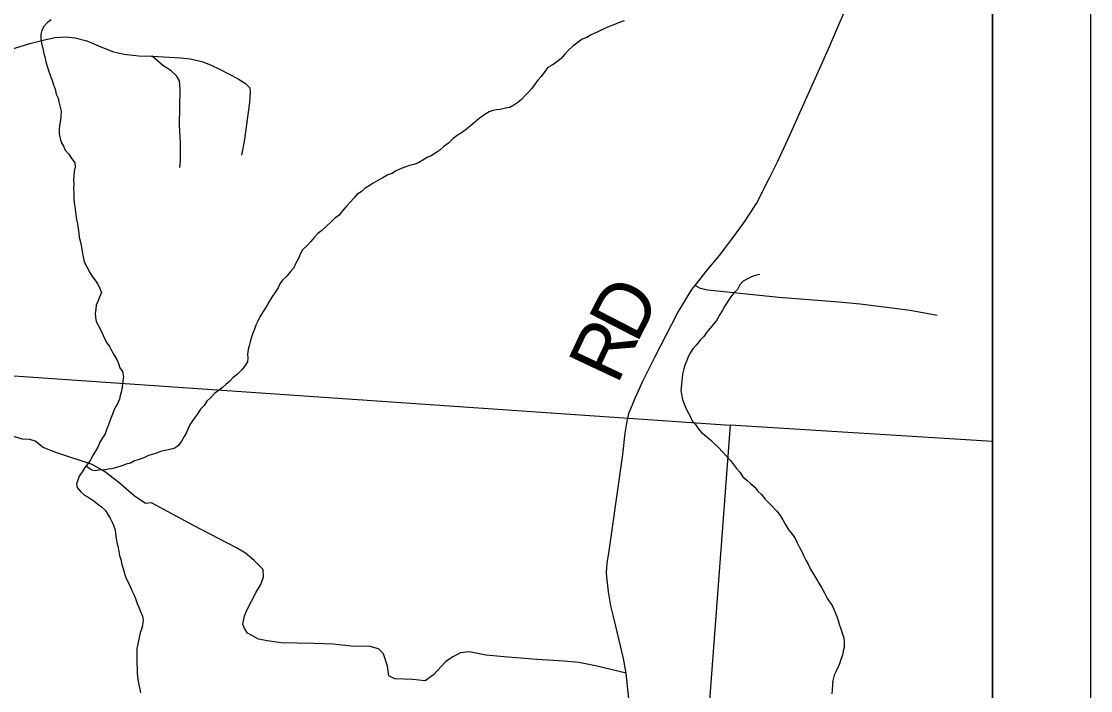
# Model space of a CAD drawing. Extents: x -13.7 to 34, y 0 to 32.3.
# Drawn here: x 29.328 to 30.417, y 19.593 to 20.274 of the extents above; entities that cross this region are included whole.
import ezdxf

# ---------------------------------------------------------------- set-up
doc = ezdxf.new("R2010")
doc.units = 0
for name, color, linetype in [('GM_X_Corporation', 7, 'Continuous'), ('GM_X_County_Road', 7, 'Continuous'), ('GM_X_County_Road_Text', 7, 'Continuous'), ('GM_X_Minor_River', 7, 'Continuous'), ('GM_X_Township_Road', 7, 'Continuous'), ('SH_Data', 7, 'Continuous')]:
    doc.layers.add(name, color=color, linetype=linetype)

msp = doc.modelspace()

# ---------------------------------------------------------------- linework, layer by layer
at = {"layer": 'GM_X_Corporation'}
for points in [[(25.5491, 14.1), (30.3167, 14.1), (30.3167, 20.877), (30.2775, 20.8796), (29.9598, 20.9), (26.0026, 20.9)], [(27.6886, 14.8962), (28.6553, 14.8354), (29.7019, 14.7755), (30.3167, 14.7354), (30.3167, 20.877), (30.2775, 20.8796), (29.9598, 20.9), (26.0026, 20.9)]]:
    msp.add_lwpolyline(points, dxfattribs=at)
for points in [[(29.0337, 19.933), (30.0496, 19.8628), (29.9735, 18.8499), (28.9612, 18.9069)], [(30.3167, 18.8265), (30.3167, 19.8464), (30.0496, 19.8628), (29.9735, 18.8499)]]:
    msp.add_lwpolyline(points, close=True, dxfattribs=at)
at = {"layer": 'GM_X_County_Road'}
msp.add_lwpolyline([(29.9468, 19.5812), (29.9436, 19.6104), (29.941, 19.6253), (29.9314, 19.6653), (29.9278, 19.6789), (29.9255, 19.6933), (29.9242, 19.7055), (29.9235, 19.7126), (29.9243, 19.7224), (29.9259, 19.7325), (29.9291, 19.7541), (29.9402, 19.833), (29.9425, 19.8548), (29.9442, 19.8649), (29.9462, 19.8747), (29.9527, 19.8904), (29.9607, 19.9078), (29.9729, 19.9321), (29.9957, 19.977), (30.0106, 20.001), (30.0139, 20.0053), (30.0261, 20.0209), (30.0388, 20.0358), (30.0531, 20.0549), (30.064, 20.07), (30.0765, 20.0886), (30.0893, 20.1141), (30.0981, 20.1317), (30.1086, 20.1544), (30.1498, 20.2461), (30.1756, 20.3066)], dxfattribs=at)
at = {"layer": 'GM_X_Minor_River'}
for points in [[(29.3578, 20.2758), (29.354, 20.2728), (29.3503, 20.269), (29.3484, 20.2652), (29.3472, 20.2606), (29.3472, 20.2568), (29.348, 20.2519), (29.3496, 20.2447), (29.3503, 20.2409), (29.3519, 20.2368), (29.3526, 20.233), (29.3538, 20.2284), (29.3553, 20.2242), (29.3568, 20.2193), (29.3584, 20.2148), (29.3599, 20.2106), (29.3618, 20.2049), (29.363, 20.2)], [(29.9415, 20.2746), (29.9373, 20.2731), (29.9335, 20.2716), (29.929, 20.2697), (29.924, 20.2678), (29.9195, 20.2659), (29.9153, 20.2636), (29.9115, 20.2621), (29.9073, 20.2601), (29.9036, 20.2575), (29.8986, 20.256), (29.8933, 20.2518), (29.8891, 20.2487), (29.885, 20.2449), (29.8812, 20.2407), (29.8774, 20.2362), (29.8713, 20.2316), (29.8676, 20.2293), (29.8638, 20.227), (29.8607, 20.2232), (29.857, 20.2179), (29.8535, 20.2141), (29.8505, 20.2103), (29.8475, 20.2058), (29.8441, 20.202), (29.8403, 20.1982), (29.8369, 20.1944), (29.8331, 20.1913), (29.8293, 20.1886), (29.8251, 20.1864), (29.8206, 20.1856), (29.8153, 20.1844), (29.8115, 20.184), (29.8077, 20.1833), (29.8039, 20.1818), (29.7986, 20.1787), (29.794, 20.1753), (29.7891, 20.1711), (29.7849, 20.1677), (29.7808, 20.1642), (29.777, 20.1612), (29.7713, 20.1578), (29.7675, 20.1547), (29.7626, 20.1502), (29.7577, 20.1467), (29.7539, 20.1429)], [(29.363, 20.2), (29.3649, 20.1958), (29.3656, 20.192), (29.3672, 20.1867), (29.368, 20.1826), (29.3676, 20.1765), (29.3672, 20.1719), (29.3665, 20.1681), (29.3661, 20.164), (29.3661, 20.1598), (29.3669, 20.1549), (29.368, 20.1511), (29.3703, 20.1469), (29.3722, 20.1431), (29.376, 20.139), (29.3783, 20.1352), (29.3821, 20.1302), (29.3822, 20.1257), (29.3814, 20.1211), (29.381, 20.1162), (29.3807, 20.1124), (29.3811, 20.1079), (29.3807, 20.1041), (29.3811, 20.0984), (29.3811, 20.0923), (29.3815, 20.0874), (29.3823, 20.0832), (29.3827, 20.0794), (29.3838, 20.0722), (29.3846, 20.0681), (29.3854, 20.0631), (29.3861, 20.0582), (29.3865, 20.0544), (29.3881, 20.048), (29.3888, 20.0442), (29.3896, 20.0396), (29.3904, 20.0343), (29.3915, 20.0294), (29.3942, 20.0241), (29.3972, 20.0184), (29.3999, 20.0139), (29.4033, 20.0097), (29.4056, 20.0059), (29.4075, 20.0021), (29.4091, 19.9979), (29.4072, 19.9934), (29.4053, 19.9888), (29.4038, 19.985), (29.4034, 19.9812), (29.4027, 19.9767), (29.4031, 19.9729), (29.4038, 19.9684), (29.4069, 19.9631), (29.4099, 19.9566), (29.4126, 19.9506), (29.4145, 19.9468), (29.4172, 19.943), (29.4195, 19.9388), (29.4221, 19.9343), (29.4248, 19.9297), (29.4263, 19.9256), (29.4279, 19.9214), (29.4305, 19.9176), (29.4317, 19.9123), (29.4309, 19.9081), (29.4302, 19.9021), (29.4295, 19.8975), (29.4283, 19.8933), (29.4276, 19.8895), (29.4253, 19.8846), (29.423, 19.8808), (29.4215, 19.877), (29.4196, 19.8724), (29.4178, 19.8675), (29.4163, 19.8633), (29.4147, 19.8592), (29.4129, 19.8542), (29.4102, 19.85), (29.4076, 19.8455), (29.4057, 19.8413), (29.4034, 19.8371), (29.4008, 19.8326), (29.3981, 19.8276), (29.3951, 19.8235), (29.3921, 19.8197), (29.3894, 19.8155), (29.3864, 19.8109), (29.3849, 19.8071), (29.3838, 19.8033), (29.3845, 19.7995), (29.388, 19.795), (29.3918, 19.7916), (29.3971, 19.7886), (29.4013, 19.7859), (29.4055, 19.7825), (29.4093, 19.7799), (29.4131, 19.7761), (29.4157, 19.7719), (29.418, 19.7681), (29.4199, 19.7643), (29.4218, 19.7602)], [(29.7539, 20.1429), (29.7497, 20.1403), (29.7448, 20.1372), (29.741, 20.1353), (29.7364, 20.1327), (29.7319, 20.13), (29.7273, 20.1285), (29.7228, 20.1273), (29.719, 20.1258), (29.7144, 20.1243), (29.7087, 20.1216), (29.7049, 20.1193), (29.7008, 20.1178), (29.6958, 20.1147), (29.6905, 20.1121), (29.686, 20.1094), (29.6818, 20.1067), (29.6776, 20.1044), (29.6735, 20.1006), (29.6697, 20.098), (29.6663, 20.0942), (29.6629, 20.0904), (29.6591, 20.0862), (29.6545, 20.0812), (29.6508, 20.0763), (29.647, 20.074), (29.6432, 20.0698), (29.6382, 20.0657), (29.6337, 20.0611), (29.6295, 20.0581), (29.6257, 20.0539), (29.6223, 20.0501), (29.6186, 20.0459), (29.614, 20.0413), (29.6114, 20.0371), (29.6099, 20.0326), (29.6068, 20.0273), (29.6049, 20.0231), (29.6015, 20.0193), (29.5978, 20.0147), (29.5936, 20.0106), (29.5909, 20.0068), (29.589, 20.0026), (29.5856, 19.9976), (29.5826, 19.9931), (29.58, 19.9889), (29.5777, 19.9843), (29.5732, 19.9775), (29.5705, 19.9733), (29.5683, 19.9688), (29.5664, 19.9646), (29.5649, 19.9608), (29.5633, 19.9566), (29.5618, 19.9524), (29.5607, 19.9479), (29.5596, 19.9437), (29.5585, 19.9399), (29.5577, 19.9354), (29.5581, 19.9316), (29.5577, 19.9274), (29.5555, 19.9236), (29.5521, 19.9194), (29.5475, 19.9145), (29.5433, 19.9114), (29.5399, 19.9076), (29.5358, 19.9042), (29.532, 19.9008), (29.5282, 19.8981), (29.5244, 19.8951), (29.521, 19.8913), (29.5164, 19.8875), (29.5138, 19.8829), (29.51, 19.8791), (29.5074, 19.8749), (29.5043, 19.8708), (29.4994, 19.8639), (29.4975, 19.8594), (29.4956, 19.8556), (29.4934, 19.8514), (29.4907, 19.8468), (29.4873, 19.8419), (29.4832, 19.8392), (29.4786, 19.8381), (29.474, 19.8373), (29.4691, 19.8362), (29.4653, 19.8346), (29.4608, 19.8331), (29.457, 19.832), (29.4524, 19.8297), (29.4475, 19.8281), (29.4429, 19.8266), (29.4388, 19.8243), (29.4342, 19.8232), (29.4297, 19.8216), (29.4243, 19.8197), (29.4198, 19.8186), (29.416, 19.8182), (29.4114, 19.817), (29.4076, 19.8174), (29.4031, 19.8166), (29.3993, 19.817)], [(30.0796, 20.0163), (30.0751, 20.0152), (30.0713, 20.014), (30.0671, 20.0121), (30.0629, 20.0095), (30.0595, 20.0057), (30.0569, 20.0011), (30.0531, 19.9977), (30.0501, 19.9935), (30.0467, 19.9886), (30.0436, 19.9836), (30.0414, 19.9794), (30.0391, 19.9756), (30.0357, 19.9696), (30.0327, 19.9658), (30.0289, 19.9612), (30.0255, 19.9574), (30.0228, 19.9532), (30.019, 19.9494), (30.0153, 19.9449), (30.0115, 19.9407), (30.0092, 19.9369), (30.0069, 19.9331), (30.0054, 19.9289), (30.0035, 19.924), (30.0024, 19.9202), (30.0009, 19.9149), (30.0005, 19.9107), (29.9998, 19.9046), (29.9994, 19.8982), (29.9998, 19.8944), (30.001, 19.8891), (30.0025, 19.8845), (30.0044, 19.8804), (30.0071, 19.875), (30.009, 19.8713), (30.0109, 19.8675), (30.0143, 19.8637), (30.017, 19.8595), (30.0204, 19.8554), (30.025, 19.8516), (30.0299, 19.8478), (30.0338, 19.8436), (30.0376, 19.8402), (30.0417, 19.8357), (30.0452, 19.8319), (30.0497, 19.827), (30.0528, 19.8228), (30.0558, 19.8187), (30.0597, 19.8149), (30.0623, 19.8103), (30.0665, 19.8069), (30.0703, 19.8035), (30.0745, 19.7997), (30.0775, 19.796), (30.0814, 19.7922), (30.0852, 19.7876), (30.0905, 19.7823), (30.097, 19.7755), (30.1004, 19.771), (30.1031, 19.7664), (30.1057, 19.7623), (30.1092, 19.7562), (30.113, 19.7517), (30.1157, 19.7475), (30.1176, 19.7433), (30.1198, 19.7392), (30.1225, 19.7342), (30.1241, 19.7301), (30.1267, 19.7255), (30.129, 19.7214), (30.1313, 19.7164), (30.1344, 19.7111), (30.1374, 19.7062), (30.1397, 19.702), (30.1424, 19.6975), (30.1458, 19.6914), (30.1485, 19.6861), (30.1538, 19.6786), (30.1565, 19.6721), (30.158, 19.6683), (30.1595, 19.6642), (30.1607, 19.6604), (30.1622, 19.6555), (30.1641, 19.6501), (30.1653, 19.6464), (30.1657, 19.641), (30.1657, 19.6365), (30.1646, 19.6327), (30.1638, 19.6289), (30.1623, 19.6244), (30.1608, 19.6198), (30.1578, 19.613), (30.1555, 19.6084), (30.154, 19.6031), (30.1536, 19.5985), (30.1533, 19.5936), (30.1529, 19.5894)], [(29.3993, 19.817), (29.3932, 19.8211)], [(29.4218, 19.7602), (29.423, 19.7564), (29.4234, 19.7526), (29.4242, 19.7477), (29.4249, 19.7435), (29.4257, 19.7397), (29.4268, 19.7344), (29.4276, 19.7302), (29.4288, 19.7261), (29.4299, 19.7211), (29.4311, 19.717), (29.4334, 19.7094), (29.4353, 19.7048), (29.4376, 19.7003), (29.4402, 19.6946), (29.4422, 19.6904), (29.4437, 19.6863), (29.4456, 19.6814), (29.4471, 19.6776), (29.4487, 19.6738), (29.4509, 19.6685), (29.4517, 19.6643), (29.451, 19.659), (29.4498, 19.6552), (29.4487, 19.6514), (29.4476, 19.6468), (29.4461, 19.64), (29.4453, 19.6358), (29.445, 19.632), (29.445, 19.6279), (29.445, 19.6237), (29.445, 19.6199), (29.4454, 19.6154), (29.4454, 19.61), (29.4462, 19.604), (29.4473, 19.5987), (29.4481, 19.5941), (29.4489, 19.5903)]]:
    msp.add_lwpolyline(points, dxfattribs=at)
at = {"layer": 'GM_X_Township_Road'}
for points in [[(29.2893, 20.2369), (29.2921, 20.2378), (29.3361, 20.2516), (29.3524, 20.2556), (29.3621, 20.2575), (29.3727, 20.2582), (29.3822, 20.2574), (29.3941, 20.2544), (29.4061, 20.2493), (29.4203, 20.2435), (29.4318, 20.2408), (29.4472, 20.239), (29.4599, 20.2388)], [(29.4599, 20.2388), (29.4608, 20.2388), (29.4895, 20.2368), (29.4996, 20.236), (29.5112, 20.2333), (29.5203, 20.2297), (29.53, 20.225), (29.5482, 20.2155), (29.5559, 20.2109), (29.5602, 20.2064), (29.5606, 20.2017), (29.56, 20.1916), (29.5543, 20.1519), (29.5519, 20.1378)], [(29.4889, 20.1254), (29.4895, 20.1319), (29.4895, 20.1378), (29.4895, 20.1505), (29.4887, 20.1685), (29.4893, 20.2052), (29.4885, 20.2135), (29.4855, 20.2186), (29.48, 20.2236), (29.4717, 20.2291), (29.4608, 20.2388)], [(30.0139, 20.0053), (30.0191, 20.0025), (30.0269, 20.0008), (30.0992, 19.9934), (30.1603, 19.9885), (30.1819, 19.9866), (30.2328, 19.9799), (30.2604, 19.9749)], [(29.7078, 19.6046), (29.7019, 19.6076), (29.7005, 19.6175), (29.6965, 19.6301), (29.6912, 19.6353), (29.6827, 19.6375), (29.6633, 19.6378), (29.645, 19.64), (29.6254, 19.6405), (29.5922, 19.6414), (29.578, 19.6433), (29.5692, 19.6451), (29.5629, 19.6485), (29.558, 19.6513), (29.5547, 19.6559), (29.5532, 19.6603), (29.5547, 19.6688), (29.5574, 19.6754), (29.562, 19.6836), (29.5667, 19.6928), (29.5716, 19.7008), (29.5743, 19.7086), (29.5738, 19.716), (29.5648, 19.7252), (29.5559, 19.7326), (29.5468, 19.7381), (29.5027, 19.7607), (29.4602, 19.7838), (29.4539, 19.7832), (29.4425, 19.7909), (29.4268, 19.8045), (29.4121, 19.8159), (29.3997, 19.823), (29.3635, 19.8347), (29.3497, 19.8402), (29.3416, 19.8468), (29.336, 19.8482), (29.3288, 19.8487), (29.3164, 19.8524)], [(29.9436, 19.6104), (29.9124, 19.6178), (29.8955, 19.6212), (29.88, 19.6225), (29.8527, 19.6245), (29.8192, 19.627), (29.8007, 19.6288), (29.7837, 19.6322), (29.7749, 19.6313), (29.7671, 19.627), (29.7594, 19.6221), (29.7474, 19.6086), (29.7388, 19.6027), (29.726, 19.604), (29.7078, 19.6046)]]:
    msp.add_lwpolyline(points, dxfattribs=at)
at = {"layer": 'SH_Data'}
for points in [[(23.4167, 21), (30.4167, 21), (30.4167, 14), (23.4167, 14)], [(23.5167, 20.9), (30.3167, 20.9), (30.3167, 14.1), (23.5167, 14.1)]]:
    msp.add_lwpolyline(points, close=True, dxfattribs=at)

# ---------------------------------------------------------------- texts
at = {"layer": 'GM_X_County_Road_Text'}
for s, rotation, p in [('D', 62.7654, (29.9541, 19.9449)), ('R', 64.7931, (29.9344, 19.9031))]:
    msp.add_text(s, height=0.0568, rotation=rotation, dxfattribs=at).set_placement(p)

doc.saveas('drawing.dxf')
